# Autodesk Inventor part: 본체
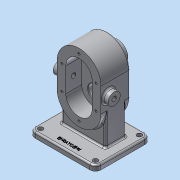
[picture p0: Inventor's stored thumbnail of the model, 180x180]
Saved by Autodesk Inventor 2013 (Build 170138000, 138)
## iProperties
Created: 2020-09
Part Number: 본체
Material: 알루미늄 6061
Document SubType Name: Modeling
Designer: Administrator
Density: 2.71 g/cm^3
Mass: 1445.8 g
Surface Area: 785.637 cm^2
Volume: 533.506 cm^3
Author: Administrator
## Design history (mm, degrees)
sketch "스케치1"
  geometry: L1 (-60, -50)-(60, -50); L2 (60, -50)-(60, 50); L3 (60, 50)-(-60, 50); L4 (-60, 50)-(-60, -50); L5 (-60, -50)-(60, 50); L6 (60, -50)-(-60, 50); 1 further point
  constraints: 12 end point, 2 midpoint, 2 parallel, 1 horizontal, 1 perpendicular
  dimensions: "d0" = 120 distance of L2.end L3.end; "d2" = 100 distance of L3.end L1.start
extrude "돌출1" new body sketch "스케치1" distance "d3" = 10; taper "d4" = 0 deg
fillet "모깎기1" dims "d5" = 10
sketch "스케치2"
  geometry: L1 (-40, -12)-(40, -12); L2 (40, -12)-(40, 25); L3 (40, 25)-(-40, 25); L4 (-40, 25)-(-40, -12); L5 (-40, -12)-(40, 25); L6 (40, -12)-(-40, 25); L7 (50, 50)-(-50, 50) reference; 3 further points
  constraints: 12 end point, 3 midpoint, 2 parallel, 1 horizontal, 1 perpendicular, 1 vertical alignment
  dimensions: "d6" = 80 distance of L1.start L1.end; "d8" = 37 distance of L1.end L2.end; "d9" = 25 distance between parallel lines of L7 L3
node "작업 평면1"
extrude "돌출2" join sketch "스케치2" distance "d11" = 142; taper "d12" = 0 deg
fillet "모깎기2" dims "d13" = 40
sketch "스케치3"
  geometry: L1 (16, 58)-(16, 102); L2 (64, 102)-(64, 58); L3 (-10, -10)-(90, -10) reference; A1 r 40 centre (40, 102) between (80, 102) and (0, 102) reference; A2 r 24 centre (40, 102) between (64, 102) and (16, 102); A3 r 24 centre (40, 58) between (16, 58) and (64, 58); 2 further points
  constraints: 4 end point, 4 point on circle, 4 tangent, 2 centre point, 2 vertical alignment, 1 concentric, 1 midpoint, 1 parallel, 1 vertical
  dimensions: "d14" = 24 radius of A2; "d16" = 44 distance of A3.centre A1.centre
extrude "돌출3" cut sketch "스케치3" distance "d17" = 21; taper "d18" = 0 deg
hole "구멍1" diameter "d21" = 17; stored, may be unused: countersink angle "d25" = 90 deg, drill point angle "d27" = 118 deg; dims "d19" = 10, "d20" = 10, "d22" = 6, "d23" = 4, "d24" = 2, "d26" = 8
hole "구멍2" diameter "d30" = 17; stored, may be unused: countersink angle "d34" = 90 deg, drill point angle "d36" = 118 deg; dims "d28" = 10, "d29" = 10, "d31" = 6, "d32" = 4, "d33" = 2, "d35" = 8
sketch "스케치4"
  geometry: L1 (80, 0)-(80, 102) reference; L2 (0, 0)-(0, 102) reference; L3 (80, 102)-(80, 58); L4 (0, 102)-(0, 58); L5 (64, 102)-(64, 58) reference; L6 (16, 58)-(16, 102) reference; A1 r 40 centre (40, 102) between (80, 102) and (0, 102) reference; A2 r 40 centre (40, 102) between (80, 102) and (0, 102); A3 r 40 centre (40, 58) between (0, 58) and (80, 58); A4 r 24 centre (40, 102) between (64, 102) and (16, 102) reference; A5 r 24 centre (40, 58) between (16, 58) and (64, 58) reference; 1 further point
  constraints: 6 tangent, 4 end point, 4 point on circle, 2 centre point, 2 point on line
  dimensions: "d37" = 44 distance of L1.end L3.end; "d38" = 44 distance of L2.end L4.end
extrude "돌출4" join sketch "스케치4" distance "d39" = 8; taper "d40" = 0 deg; dims "d41" = 45, "d42" = 0
sketch "스케치5"
  geometry: L1 (24, -44)-(24, 0) reference; L2 (-24, 0)-(-24, -44) reference; C1 r 8.5 at (0, 0) reference; C2 r 8.5 at (0, -44) reference; A1 r 24 centre (0, 0) between (24, 0) and (-24, 0) reference; A2 r 24 centre (0, -44) between (-24, -44) and (24, -44) reference; 1 further point
extrude "돌출5" join sketch "스케치5" distance "d43" = 8; taper "d44" = 0 deg
hole "구멍3" diameter "d47" = 25; stored, may be unused: countersink angle "d51" = 90 deg, drill point angle "d53" = 0 deg; dims "d45" = 10, "d46" = 10, "d48" = 6, "d49" = 4, "d50" = 2, "d52" = 15
sketch "스케치6"
  geometry: C1 r 8.5 at (40, -102) reference; C2 r 19 at (40, -102); 1 further point
  constraints: 1 centre point
  dimensions: "d63" = 38 diameter of C2
extrude "돌출6" join sketch "스케치6" distance "d65" = 17; taper "d66" = 0 deg
hole "구멍5" diameter "d69" = 28; stored, may be unused: countersink angle "d73" = 90 deg, drill point angle "d75" = 0 deg; dims "d67" = 10, "d68" = 10, "d70" = 6, "d71" = 4, "d72" = 2, "d74" = 7.3
hole "구멍6" diameter "d78" = 17; stored, may be unused: countersink angle "d82" = 90 deg, drill point angle "d84" = 0 deg; dims "d76" = 10, "d77" = 10, "d79" = 6, "d80" = 4, "d81" = 2, "d83" = 7.3
sketch "스케치7"
  geometry: C1 r 8.5 at (40, 58) reference; 1 further point
extrude "돌출7" join sketch "스케치7" stored distance "d85" = 17; taper "d86" = 0 deg
hole "구멍7" diameter "d89" = 25; stored, may be unused: countersink angle "d93" = 90 deg, drill point angle "d95" = 0 deg; dims "d87" = 10, "d88" = 10, "d90" = 6, "d91" = 4, "d92" = 2, "d94" = 15
sketch "스케치8"
  geometry: L1 (-10, 52)-(-10, -28) reference; L2 (58, 45)-(102, 45) reference; L3 (102, -8)-(58, -8) reference; C1 r 11 at (80, 6); 1 further point
  constraints: 1 centre point
  dimensions: "d96" = 90 distance from line of C1.centre L1; "d97" = 22 diameter of C1; "d181" = 14 distance from line of C1.centre L3
extrude "돌출8" join sketch "스케치8" distance "d99" = 10; taper "d100" = 0 deg
hole "구멍8" diameter "d103" = 8.376; stored, may be unused: countersink angle "d107" = 90 deg, drill point angle "d109" = 0 deg; dims "d101" = 10, "d102" = 10, "d104" = 6, "d105" = 4, "d106" = 2, "d108" = 15
sketch "스케치9"
  geometry: C1 r 12.5 at (40, 58) reference; A1 r 24 centre (40, 102) between (64, 102) and (16, 102) reference; 7 further points
  constraints: 3 horizontal alignment, 2 vertical alignment
  dimensions: "d110" = 31 distance of A1.centre point (40, 133); "d118" = 44 distance of point (71, 58) point (71, 102); "d119" = 31 distance of A1.centre point (71, 102); "d120" = 31 distance of A1.centre point (9, 102); "d121" = 31 distance of C1.centre point (9, 58); "d122" = 31 distance of point (40, 27) C1.centre; "d123" = 31 distance of point (71, 58) C1.centre
hole "구멍9" sketch "스케치9" diameter "d111" = 4.134; stored, may be unused: countersink angle "d115" = 90 deg, drill point angle "d117" = 118 deg; dims "d112" = 10, "d113" = 4, "d114" = 2, "d116" = 12
hole "구멍10" sketch "스케치9" diameter "d124" = 4.134; stored, may be unused: countersink angle "d128" = 90 deg, drill point angle "d130" = 118 deg; dims "d125" = 10, "d126" = 4, "d127" = 2, "d129" = 12
fillet "모깎기3" dims "d131" = 3
fillet "모깎기4" dims "d132" = 3
fillet "모깎기5" dims "d133" = 3
fillet "모깎기6" dims "d134" = 3
fillet "모깎기7" dims "d135" = 3
fillet "모깎기8" dims "d136" = 3
hole "구멍11" diameter "d139" = 9; stored, may be unused: countersink angle "d143" = 90 deg, drill point angle "d145" = 118 deg; dims "d137" = 10, "d138" = 10, "d140" = 9, "d141" = 4, "d142" = 2, "d144" = 12
hole "구멍12" diameter "d148" = 9; stored, may be unused: countersink angle "d152" = 90 deg, drill point angle "d154" = 118 deg; dims "d146" = 10, "d147" = 10, "d149" = 9, "d150" = 4, "d151" = 2, "d153" = 12
hole "구멍13" diameter "d157" = 9; stored, may be unused: countersink angle "d161" = 90 deg, drill point angle "d163" = 118 deg; dims "d155" = 10, "d156" = 10, "d158" = 9, "d159" = 4, "d160" = 2, "d162" = 12
hole "구멍14" diameter "d166" = 9; stored, may be unused: countersink angle "d170" = 90 deg, drill point angle "d172" = 118 deg; dims "d164" = 10, "d165" = 10, "d167" = 9, "d168" = 4, "d169" = 2, "d171" = 12
sketch "스케치10"
  geometry: L1 (-50, -50)-(50, -50) reference; L2 (-60, 40)-(-60, -40) reference; 2 further points
  constraints: 1 other
  dimensions: "d173" = 12 distance from line of L1 point (0, -38); "d174" = 60 distance from line of point (0, -38) L2
feature "엠보싱1" sketch "스케치10" dims "d2" = 100, "d175" = 0.5, "d176" = 0
fillet "모깎기9" dims "d177" = 3
chamfer "모따기1" distance "d178" = 1; stored, may be unused: second distance "d179" = 2, angle "d180" = 45 deg
fillet "모깎기10" dims "d182" = 0.5
chamfer "모따기2" distance "d183" = 0.7; stored, may be unused: second distance "d184" = 2, angle "d185" = 30 deg
node "솔리드1"
mirror "대칭1"
node "투영된 루프1"
